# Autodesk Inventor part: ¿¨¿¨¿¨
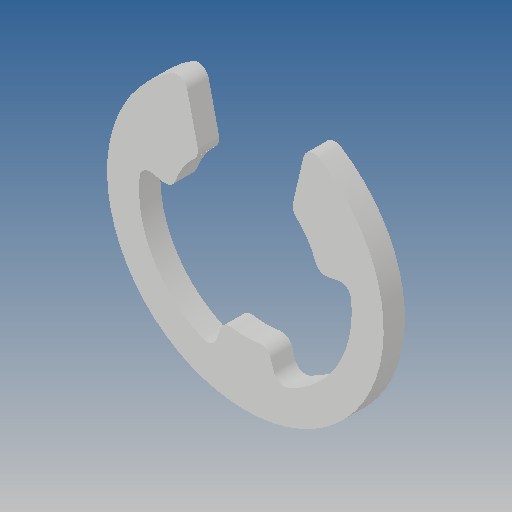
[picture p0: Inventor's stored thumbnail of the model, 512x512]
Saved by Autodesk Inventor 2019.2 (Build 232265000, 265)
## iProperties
Created: 2013-07
Part Number: ¿¨¿¨¿¨
Material: Ogólny
Document SubType Name: Modeling
Designer: CADENGINEERING4
Density: 1 g/cm^3
Appearance: Domyślna
Author: CADENGINEERING4
Revision Number: ÈÎºÎ
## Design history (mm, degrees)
feature "Í¹Ì¨-À­Éì1"
node "Bryła1"
